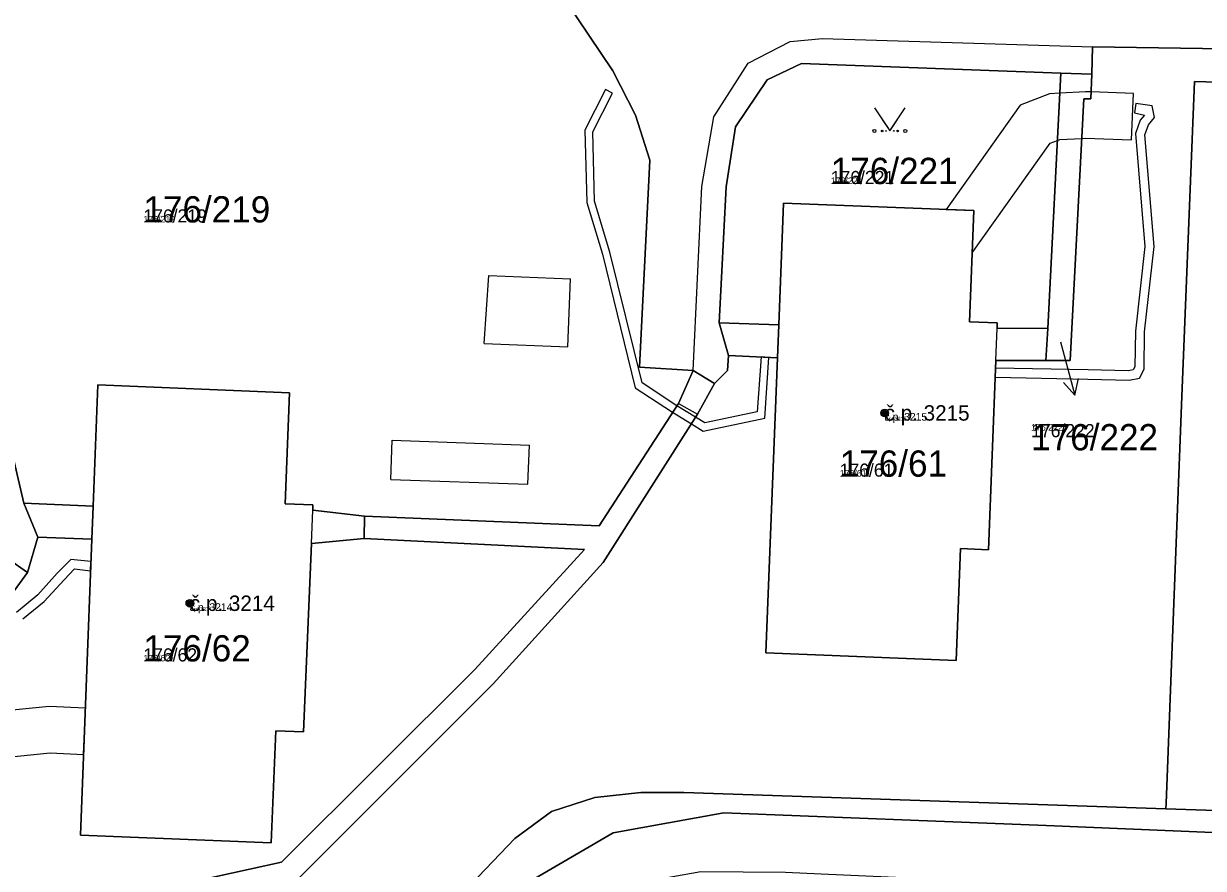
# Model space of a CAD drawing. Extents: x -759873 to -758487, y -975024 to -973516.
# Drawn here: x -759456.7 to -759380.2, y -974836.2 to -974781.5 of the extents above; entities that cross this region are included whole.
import ezdxf

# ---------------------------------------------------------------- set-up
doc = ezdxf.new("R2010")
doc.units = 0
for name, color, linetype in [('KAT_02_hranice parcel', 7, 'Continuous'), ('KAT_03_1000_st čísla parcelní', 7, 'Continuous'), ('KAT_03_1000_čísla parcelní', 7, 'Continuous'), ('KAT_03_1000_čísla popisná', 7, 'Continuous'), ('KAT_03_250_st čísla parcelní', 7, 'Continuous'), ('KAT_03_250_čísla parcelní', 7, 'Continuous'), ('KAT_03_250_čísla popisná', 7, 'Continuous'), ('KAT_03_500_st čísla parcelní', 7, 'Continuous'), ('KAT_03_500_čísla parcelní', 7, 'Continuous'), ('KAT_03_500_čísla popisná', 7, 'Continuous'), ('KAT_04_vnitřní kresba', 7, 'Continuous'), ('KAT_05_1000_značky kultur', 7, 'Continuous'), ('KAT_05_250_značky kultur', 7, 'Continuous'), ('KAT_05_500_značky kultur', 7, 'Continuous'), ('KAT_07_1000_značky budov', 7, 'Continuous'), ('KAT_07_250_značky budov', 7, 'Continuous'), ('KAT_07_500_značky budov', 7, 'Continuous'), ('KAT_10_věcná břemena', 7, 'Continuous'), ('KAT_12_pomocná šipka', 7, 'Continuous'), ('KAT_14_plocha_budovy', 7, 'Continuous'), ('KAT_14_plocha_pozemek', 7, 'Continuous')]:
    doc.layers.add(name, color=color, linetype=linetype)

msp = doc.modelspace()

# ---------------------------------------------------------------- linework, layer by layer
at = {"layer": 'KAT_02_hranice parcel'}
for p, q in [((-759390.33, -974801.21), (-759389.48, -974784.67)), ((-759387.48, -974784.74), (-759389.48, -974784.67)), ((-759411.6, -974800.85), (-759411.01, -974802.96)), ((-759390.44, -974803.28), (-759390.33, -974801.21)), ((-759411.92, -974804.78), (-759413.3, -974803.92)), ((-759456.64, -974812.53), (-759455.74, -974814.72)), ((-759434.61, -974814.81), (-759434.58, -974813.37)), ((-759456.41, -974817.02), (-759455.74, -974814.72)), ((-759457.64, -974816.15), (-759456.41, -974817.02))]:
    msp.add_line(p, q, dxfattribs=at)
for points in [[(-759413.3, -974803.92), (-759416.77, -974803.71), (-759416.1, -974790.31), (-759417.02, -974787.38), (-759418.5, -974784.52), (-759428.57, -974769.5), (-759431.12, -974766.84), (-759432.32, -974766.17)], [(-759456.64, -974812.53), (-759457.57, -974808.53), (-759462.26, -974802.53), (-759468.11, -974797.84), (-759474.14, -974794.38), (-759477.74, -974791.66), (-759479.98, -974789.1), (-759481.11, -974784.96), (-759479.77, -974780.42), (-759476.24, -974777.5), (-759473.09, -974776.05)], [(-759360.13, -974783.47), (-759374.6, -974783.16), (-759387.42, -974782.97), (-759387.48, -974784.74)], [(-759389.48, -974784.67), (-759406.27, -974784.05), (-759408.49, -974785.09), (-759410.56, -974788.15), (-759411.15, -974792.03), (-759411.6, -974800.85)], [(-759387.48, -974784.74), (-759387.54, -974786.34), (-759387.99, -974786.32), (-759388.88, -974803.28), (-759390.44, -974803.28)], [(-759382.67, -974832.32), (-759382.66, -974831.98), (-759382.28, -974822.37), (-759381.65, -974805.61), (-759380.83, -974785.21), (-759360.2, -974785.81)], [(-759382.67, -974832.32), (-759358.04, -974833.14), (-759286.08, -974836), (-759287.93, -974822.96), (-759288.84, -974816.61), (-759289.72, -974807.13), (-759291.76, -974802.52), (-759298.13, -974787.72), (-759322.87, -974786.95)], [(-759390.33, -974801.21), (-759393.61, -974801.18), (-759393.6, -974800.85), (-759395.4, -974800.78), (-759395.12, -974793.57), (-759407.44, -974793.1), (-759407.75, -974800.97), (-759411.6, -974800.85)], [(-759411.01, -974802.96), (-759411.07, -974803.92), (-759411.92, -974804.78)], [(-759411.01, -974802.96), (-759407.83, -974803.1), (-759408.59, -974822.23), (-759396.25, -974822.71), (-759395.97, -974815.47), (-759394.17, -974815.54), (-759393.69, -974803.28), (-759390.44, -974803.28)], [(-759413.3, -974803.92), (-759414.25, -974806.06), (-759419.38, -974814), (-759434.58, -974813.37)], [(-759522.73, -974853.07), (-759508.22, -974850.21), (-759486.35, -974846.03), (-759478.35, -974845.69), (-759475.89, -974845.29), (-759439.14, -974837.12), (-759426.25, -974824.24), (-759419.13, -974816.38), (-759413.01, -974806.77), (-759411.92, -974804.78)], [(-759434.58, -974813.37), (-759437.93, -974812.98), (-759437.92, -974812.63), (-759439.72, -974812.56), (-759439.43, -974805.38), (-759451.85, -974804.87), (-759452.15, -974812.73), (-759456.64, -974812.53)], [(-759434.61, -974814.81), (-759420.32, -974815.53), (-759427.43, -974823.31), (-759439.96, -974835.78), (-759476.18, -974843.76), (-759458.03, -974819.25), (-759456.41, -974817.02)], [(-759455.74, -974814.72), (-759452.24, -974814.85), (-759452.98, -974834.03), (-759440.62, -974834.53), (-759440.32, -974827.27), (-759438.52, -974827.35), (-759438.02, -974815.13), (-759434.61, -974814.81)], [(-759443.37, -974853.62), (-759424.85, -974834.26), (-759422.46, -974832.5), (-759419.67, -974831.59), (-759416.69, -974831.27), (-759413.9, -974831.28), (-759382.67, -974832.32)], [(-759281.55, -974837.72), (-759288.97, -974837.7), (-759308.21, -974836.87), (-759325.02, -974836.15), (-759358.04, -974834.77), (-759390.43, -974833.42), (-759411.31, -974832.59), (-759418.48, -974833.88), (-759427.06, -974838.9), (-759442.22, -974854.65)]]:
    msp.add_lwpolyline(points, dxfattribs=at)
at = {"layer": 'KAT_03_1000_čísla popisná'}
for centre in [(-759400.89, -974806.68), (-759445.89, -974819.01)]:
    msp.add_circle(centre, 0.25, dxfattribs=at)
at = {"layer": 'KAT_03_250_čísla popisná'}
for centre in [(-759400.89, -974806.68), (-759445.89, -974819.01)]:
    msp.add_circle(centre, 0.0625, dxfattribs=at)
at = {"layer": 'KAT_03_500_čísla popisná'}
for centre in [(-759400.89, -974806.68), (-759445.89, -974819.01)]:
    msp.add_circle(centre, 0.125, dxfattribs=at)
at = {"layer": 'KAT_04_vnitřní kresba'}
for p, q in [((-759409.72, -974784.02), (-759407.01, -974782.61)), ((-759407.01, -974782.61), (-759404.91, -974782.43)), ((-759404.91, -974782.43), (-759387.42, -974782.97)), ((-759411.96, -974787.5), (-759409.72, -974784.02)), ((-759412.73, -974792), (-759411.96, -974787.5)), ((-759413.3, -974803.92), (-759412.73, -974792)), ((-759426.82, -974802.18), (-759426.53, -974797.78)), ((-759426.53, -974797.78), (-759421.23, -974798)), ((-759421.42, -974802.4), (-759421.23, -974798)), ((-759407.83, -974803.1), (-759407.75, -974800.97)), ((-759393.69, -974803.28), (-759393.61, -974801.18)), ((-759426.82, -974802.18), (-759421.42, -974802.4)), ((-759414.25, -974806.06), (-759413.01, -974806.77)), ((-759432.88, -974811), (-759432.78, -974808.45)), ((-759432.78, -974808.45), (-759423.89, -974808.76)), ((-759423.99, -974811.3), (-759423.89, -974808.76)), ((-759432.88, -974811), (-759423.99, -974811.3)), ((-759452.24, -974814.85), (-759452.15, -974812.73)), ((-759438.02, -974815.13), (-759437.93, -974812.98))]:
    msp.add_line(p, q, dxfattribs=at)
at = {"layer": 'KAT_05_1000_značky kultur'}
msp.add_lwpolyline([(-759401.55, -974786.909), (-759400.55, -974788.41), (-759399.55, -974786.909)], dxfattribs=at)
for centre in [(-759401.55, -974788.409), (-759399.55, -974788.409)]:
    msp.add_circle(centre, 0.1, dxfattribs=at)
at = {"layer": 'KAT_05_250_značky kultur'}
msp.add_lwpolyline([(-759400.8, -974788.035), (-759400.55, -974788.41), (-759400.3, -974788.035)], dxfattribs=at)
for centre in [(-759400.8, -974788.41), (-759400.3, -974788.41)]:
    msp.add_circle(centre, 0.025, dxfattribs=at)
at = {"layer": 'KAT_05_500_značky kultur'}
msp.add_lwpolyline([(-759401.05, -974787.66), (-759400.55, -974788.41), (-759400.05, -974787.66)], dxfattribs=at)
for centre in [(-759401.05, -974788.41), (-759400.05, -974788.41)]:
    msp.add_circle(centre, 0.05, dxfattribs=at)
at = {"layer": 'KAT_07_1000_značky budov'}
for centre in [(-759400.897, -974806.679), (-759445.897, -974819.009)]:
    msp.add_circle(centre, 0.175, dxfattribs=at)
at = {"layer": 'KAT_07_250_značky budov'}
for centre in [(-759400.892, -974806.68), (-759445.892, -974819.01)]:
    msp.add_circle(centre, 0.0437, dxfattribs=at)
at = {"layer": 'KAT_07_500_značky budov'}
for centre in [(-759400.893, -974806.68), (-759445.893, -974819.01)]:
    msp.add_circle(centre, 0.0875, dxfattribs=at)
at = {"layer": 'KAT_10_věcná břemena'}
for points in [[(-759418.52, -974785.96), (-759418.96, -974785.73), (-759420.3, -974788.36), (-759420.18, -974793.04), (-759419.16, -974796.4), (-759417.04, -974805.05), (-759414.62, -974806.63), (-759413.4, -974807.39), (-759412.64, -974807.87), (-759408.66, -974807.01), (-759408.38, -974803.08), (-759408.88, -974803.05), (-759409.14, -974806.6), (-759412.54, -974807.33), (-759413.13, -974806.96), (-759414.35, -974806.21), (-759416.6, -974804.74), (-759418.68, -974796.26), (-759419.68, -974792.96), (-759419.8, -974788.46)], [(-759395.23, -974796.31), (-759390.17, -974789.21), (-759389.7, -974789.02), (-759389.55, -974788.96), (-759388.12, -974788.89), (-759387.87, -974788.87), (-759384.89, -974788.99), (-759384.77, -974785.99), (-759387.52, -974785.88), (-759387.89, -974785.87), (-759389.55, -974785.96), (-759390.21, -974786), (-759392.11, -974786.75), (-759396.91, -974793.5), (-759395.12, -974793.57)], [(-759393.71, -974803.77), (-759393.73, -974804.37), (-759387.73, -974804.49), (-759385.06, -974804.56), (-759384.39, -974804.43), (-759384.09, -974803.84), (-759384.05, -974801.42), (-759383.44, -974795.89), (-759384.04, -974788.66), (-759383.81, -974788.01), (-759383.42, -974787.54), (-759383.57, -974786.78), (-759384.62, -974786.64), (-759384.7, -974787.24), (-759384.06, -974787.38), (-759384.35, -974787.71), (-759384.64, -974788.58), (-759384.04, -974795.89), (-759384.65, -974801.38), (-759384.69, -974803.7), (-759384.79, -974803.89), (-759385.12, -974803.96), (-759387.71, -974803.89)], [(-759452.66, -974825.8), (-759455.01, -974825.71), (-759461.5, -974826.35), (-759462.88, -974825.8), (-759464.44, -974825.18), (-759465.02, -974824.95), (-759467.99, -974824.38), (-759478.06, -974823.86), (-759479.14, -974823.81), (-759482.83, -974824.01), (-759486.13, -974823.61), (-759488.21, -974823.29), (-759488.32, -974826.11), (-759486.73, -974826.55), (-759482.93, -974827.03), (-759479.14, -974826.81), (-759478.22, -974826.86), (-759468.35, -974827.36), (-759466.34, -974827.75), (-759465.86, -974827.85), (-759464.73, -974828.3), (-759461.94, -974829.41), (-759454.93, -974828.71), (-759452.78, -974828.8)]]:
    msp.add_lwpolyline(points, close=True, dxfattribs=at)
msp.add_lwpolyline([(-759456.7, -974820.02), (-759455.32, -974818.9), (-759454.04, -974817.49), (-759453.37, -974816.79), (-759452.32, -974816.9), (-759452.3, -974816.3), (-759453.59, -974816.17), (-759454.48, -974817.07), (-759455.74, -974818.46), (-759457.12, -974819.6)], dxfattribs=at)
at = {"layer": 'KAT_12_pomocná šipka'}
for p, q in [((-759389.49, -974802.07), (-759389.34, -974802.64)), ((-759389.34, -974802.64), (-759388.563, -974805.539)), ((-759388.563, -974805.539), (-759389.306, -974804.701)), ((-759388.563, -974805.539), (-759388.339, -974804.442))]:
    msp.add_line(p, q, dxfattribs=at)
at = {"layer": 'KAT_14_plocha_budovy'}
for points in [[(-759395.4, -974800.78), (-759395.12, -974793.57), (-759407.44, -974793.1), (-759407.75, -974800.97), (-759407.83, -974803.1), (-759408.59, -974822.23), (-759396.25, -974822.71), (-759395.97, -974815.47), (-759394.17, -974815.54), (-759393.69, -974803.28), (-759393.61, -974801.18), (-759393.6, -974800.85)], [(-759439.72, -974812.56), (-759439.43, -974805.38), (-759451.85, -974804.87), (-759452.15, -974812.73), (-759452.24, -974814.85), (-759452.98, -974834.03), (-759440.62, -974834.53), (-759440.32, -974827.27), (-759438.52, -974827.35), (-759438.02, -974815.13), (-759437.93, -974812.98), (-759437.92, -974812.63)]]:
    msp.add_lwpolyline(points, close=True, dxfattribs=at)
at = {"layer": 'KAT_14_plocha_pozemek'}
for points in [[(-759457.57, -974808.53), (-759456.64, -974812.53), (-759452.15, -974812.73), (-759451.85, -974804.87), (-759439.43, -974805.38), (-759439.72, -974812.56), (-759437.92, -974812.63), (-759437.93, -974812.98), (-759434.58, -974813.37), (-759419.38, -974814), (-759414.25, -974806.06), (-759413.3, -974803.92), (-759416.77, -974803.71), (-759416.1, -974790.31), (-759417.02, -974787.38), (-759418.5, -974784.52), (-759428.57, -974769.5), (-759431.12, -974766.84), (-759432.32, -974766.17), (-759452, -974776.85), (-759459.82, -974776.57)], [(-759428.57, -974769.5), (-759418.5, -974784.52), (-759417.02, -974787.38), (-759416.1, -974790.31), (-759416.77, -974803.71), (-759413.3, -974803.92), (-759411.92, -974804.78), (-759411.07, -974803.92), (-759411.01, -974802.96), (-759411.6, -974800.85), (-759411.15, -974792.03), (-759410.56, -974788.15), (-759408.49, -974785.09), (-759406.27, -974784.05), (-759389.48, -974784.67), (-759387.48, -974784.74), (-759387.42, -974782.97), (-759374.6, -974783.16)], [(-759374.6, -974783.16), (-759387.42, -974782.97), (-759387.48, -974784.74), (-759387.54, -974786.34), (-759387.99, -974786.32), (-759388.88, -974803.28), (-759390.44, -974803.28), (-759393.69, -974803.28), (-759394.17, -974815.54), (-759395.97, -974815.47), (-759396.25, -974822.71), (-759408.59, -974822.23), (-759407.83, -974803.1), (-759411.01, -974802.96), (-759411.07, -974803.92), (-759411.92, -974804.78), (-759413.01, -974806.77), (-759419.13, -974816.38), (-759426.25, -974824.24), (-759439.14, -974837.12), (-759475.89, -974845.29)], [(-759459.93, -974855.14), (-759445.5, -974855.85), (-759443.37, -974853.62), (-759424.85, -974834.26), (-759422.46, -974832.5), (-759419.67, -974831.59), (-759416.69, -974831.27), (-759413.9, -974831.28), (-759382.67, -974832.32), (-759382.66, -974831.98), (-759382.28, -974822.37), (-759381.65, -974805.61), (-759380.83, -974785.21), (-759360.2, -974785.81)], [(-759360.2, -974785.81), (-759380.83, -974785.21), (-759381.65, -974805.61), (-759382.28, -974822.37), (-759382.66, -974831.98), (-759382.67, -974832.32), (-759358.04, -974833.14)], [(-759475.89, -974845.29), (-759439.14, -974837.12), (-759426.25, -974824.24), (-759419.13, -974816.38), (-759413.01, -974806.77), (-759411.92, -974804.78), (-759413.3, -974803.92), (-759414.25, -974806.06), (-759419.38, -974814), (-759434.58, -974813.37), (-759434.61, -974814.81), (-759420.32, -974815.53), (-759427.43, -974823.31), (-759439.96, -974835.78), (-759476.18, -974843.76)], [(-759457.64, -974816.15), (-759456.41, -974817.02), (-759455.74, -974814.72), (-759456.64, -974812.53), (-759457.57, -974808.53)], [(-759458.03, -974819.25), (-759456.41, -974817.02), (-759457.64, -974816.15)], [(-759286.08, -974836), (-759358.04, -974833.14), (-759382.67, -974832.32), (-759413.9, -974831.28), (-759416.69, -974831.27), (-759419.67, -974831.59), (-759422.46, -974832.5), (-759424.85, -974834.26), (-759443.37, -974853.62), (-759442.22, -974854.65), (-759427.06, -974838.9), (-759418.48, -974833.88), (-759411.31, -974832.59), (-759390.43, -974833.42), (-759358.04, -974834.77), (-759325.02, -974836.15), (-759308.21, -974836.87), (-759288.97, -974837.7)], [(-759358.04, -974834.77), (-759390.43, -974833.42), (-759411.31, -974832.59), (-759418.48, -974833.88), (-759427.06, -974838.9), (-759442.22, -974854.65), (-759439.77, -974856.85), (-759424.46, -974841.28), (-759417.27, -974837.18), (-759412.8, -974836.38), (-759407.32, -974836.43), (-759405.01, -974836.55), (-759392.95, -974837.08), (-759390.6, -974837.16), (-759378.65, -974837.7)]]:
    msp.add_lwpolyline(points, dxfattribs=at)
for points in [[(-759389.48, -974784.67), (-759406.27, -974784.05), (-759408.49, -974785.09), (-759410.56, -974788.15), (-759411.15, -974792.03), (-759411.6, -974800.85), (-759407.75, -974800.97), (-759407.44, -974793.1), (-759395.12, -974793.57), (-759395.4, -974800.78), (-759393.6, -974800.85), (-759393.61, -974801.18), (-759390.33, -974801.21)], [(-759387.48, -974784.74), (-759389.48, -974784.67), (-759390.33, -974801.21), (-759390.44, -974803.28), (-759388.88, -974803.28), (-759387.99, -974786.32), (-759387.54, -974786.34)], [(-759390.33, -974801.21), (-759393.61, -974801.18), (-759393.6, -974800.85), (-759395.4, -974800.78), (-759395.12, -974793.57), (-759407.44, -974793.1), (-759407.75, -974800.97), (-759411.6, -974800.85), (-759411.01, -974802.96), (-759407.83, -974803.1), (-759408.59, -974822.23), (-759396.25, -974822.71), (-759395.97, -974815.47), (-759394.17, -974815.54), (-759393.69, -974803.28), (-759390.44, -974803.28)], [(-759455.74, -974814.72), (-759452.24, -974814.85), (-759452.98, -974834.03), (-759440.62, -974834.53), (-759440.32, -974827.27), (-759438.52, -974827.35), (-759438.02, -974815.13), (-759434.61, -974814.81), (-759434.58, -974813.37), (-759437.93, -974812.98), (-759437.92, -974812.63), (-759439.72, -974812.56), (-759439.43, -974805.38), (-759451.85, -974804.87), (-759452.15, -974812.73), (-759456.64, -974812.53)], [(-759434.61, -974814.81), (-759438.02, -974815.13), (-759438.52, -974827.35), (-759440.32, -974827.27), (-759440.62, -974834.53), (-759452.98, -974834.03), (-759452.24, -974814.85), (-759455.74, -974814.72), (-759456.41, -974817.02), (-759458.03, -974819.25), (-759476.18, -974843.76), (-759439.96, -974835.78), (-759427.43, -974823.31), (-759420.32, -974815.53)]]:
    msp.add_lwpolyline(points, close=True, dxfattribs=at)

# ---------------------------------------------------------------- texts
at = {"layer": 'KAT_03_1000_st čísla parcelní'}
for s, p in [('176/61', (-759403.8, -974810.809)), ('176/62', (-759448.9, -974822.78))]:
    msp.add_text(s, height=1.7, dxfattribs=at).set_placement(p)
at = {"layer": 'KAT_03_1000_čísla parcelní'}
for s, p in [('176/221', (-759404.38, -974791.85)), ('176/219', (-759448.9, -974794.34)), ('176/222', (-759391.4, -974809.103))]:
    msp.add_text(s, height=1.7, dxfattribs=at).set_placement(p)
at = {"layer": 'KAT_03_1000_čísla popisná'}
for s, p in [('č.p. 3215', (-759400.89, -974807.18)), ('č.p. 3214', (-759445.89, -974819.51))]:
    msp.add_text(s, height=1, dxfattribs=at).set_placement(p)
at = {"layer": 'KAT_03_250_st čísla parcelní'}
for s, p in [('176/61', (-759403.8, -974810.809)), ('176/62', (-759448.9, -974822.78))]:
    msp.add_text(s, height=0.425, dxfattribs=at).set_placement(p)
at = {"layer": 'KAT_03_250_čísla parcelní'}
for s, p in [('176/221', (-759404.38, -974791.85)), ('176/219', (-759448.9, -974794.34)), ('176/222', (-759391.4, -974807.828))]:
    msp.add_text(s, height=0.425, dxfattribs=at).set_placement(p)
at = {"layer": 'KAT_03_250_čísla popisná'}
for s, p in [('č.p. 3215', (-759400.89, -974807.18)), ('č.p. 3214', (-759445.89, -974819.51))]:
    msp.add_text(s, height=0.25, dxfattribs=at).set_placement(p)
at = {"layer": 'KAT_03_500_st čísla parcelní'}
for s, p in [('176/61', (-759403.8, -974810.809)), ('176/62', (-759448.9, -974822.78))]:
    msp.add_text(s, height=0.85, dxfattribs=at).set_placement(p)
at = {"layer": 'KAT_03_500_čísla parcelní'}
for s, p in [('176/221', (-759404.38, -974791.85)), ('176/219', (-759448.9, -974794.34)), ('176/222', (-759391.4, -974808.253))]:
    msp.add_text(s, height=0.85, dxfattribs=at).set_placement(p)
at = {"layer": 'KAT_03_500_čísla popisná'}
for s, p in [('č.p. 3215', (-759400.89, -974807.18)), ('č.p. 3214', (-759445.89, -974819.51))]:
    msp.add_text(s, height=0.5, dxfattribs=at).set_placement(p)

doc.saveas('drawing.dxf')
